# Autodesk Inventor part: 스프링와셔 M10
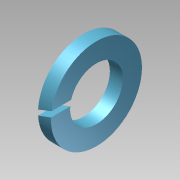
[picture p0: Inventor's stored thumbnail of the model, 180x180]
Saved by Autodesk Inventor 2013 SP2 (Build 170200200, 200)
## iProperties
Created: 2025-04
Part Number: 스프링와셔 M10
Material: Generic
Document SubType Name: Modeling
Designer: i
Density: 1 g/cm^3
Author: i
변환 표준: STEP AP214IS
전처리기: Build: 200, Release: 2013 SP2 Update 6 - Date: Thu 07/17/2014
전송 단위: 밀리미터
불확실성: 0.01
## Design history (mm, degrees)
node "스프링와셔 M101"
body "Solid1"
node "기준1"
